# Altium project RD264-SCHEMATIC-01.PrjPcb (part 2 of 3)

## Sheet 4.SchDoc
size 420 x 297 mm
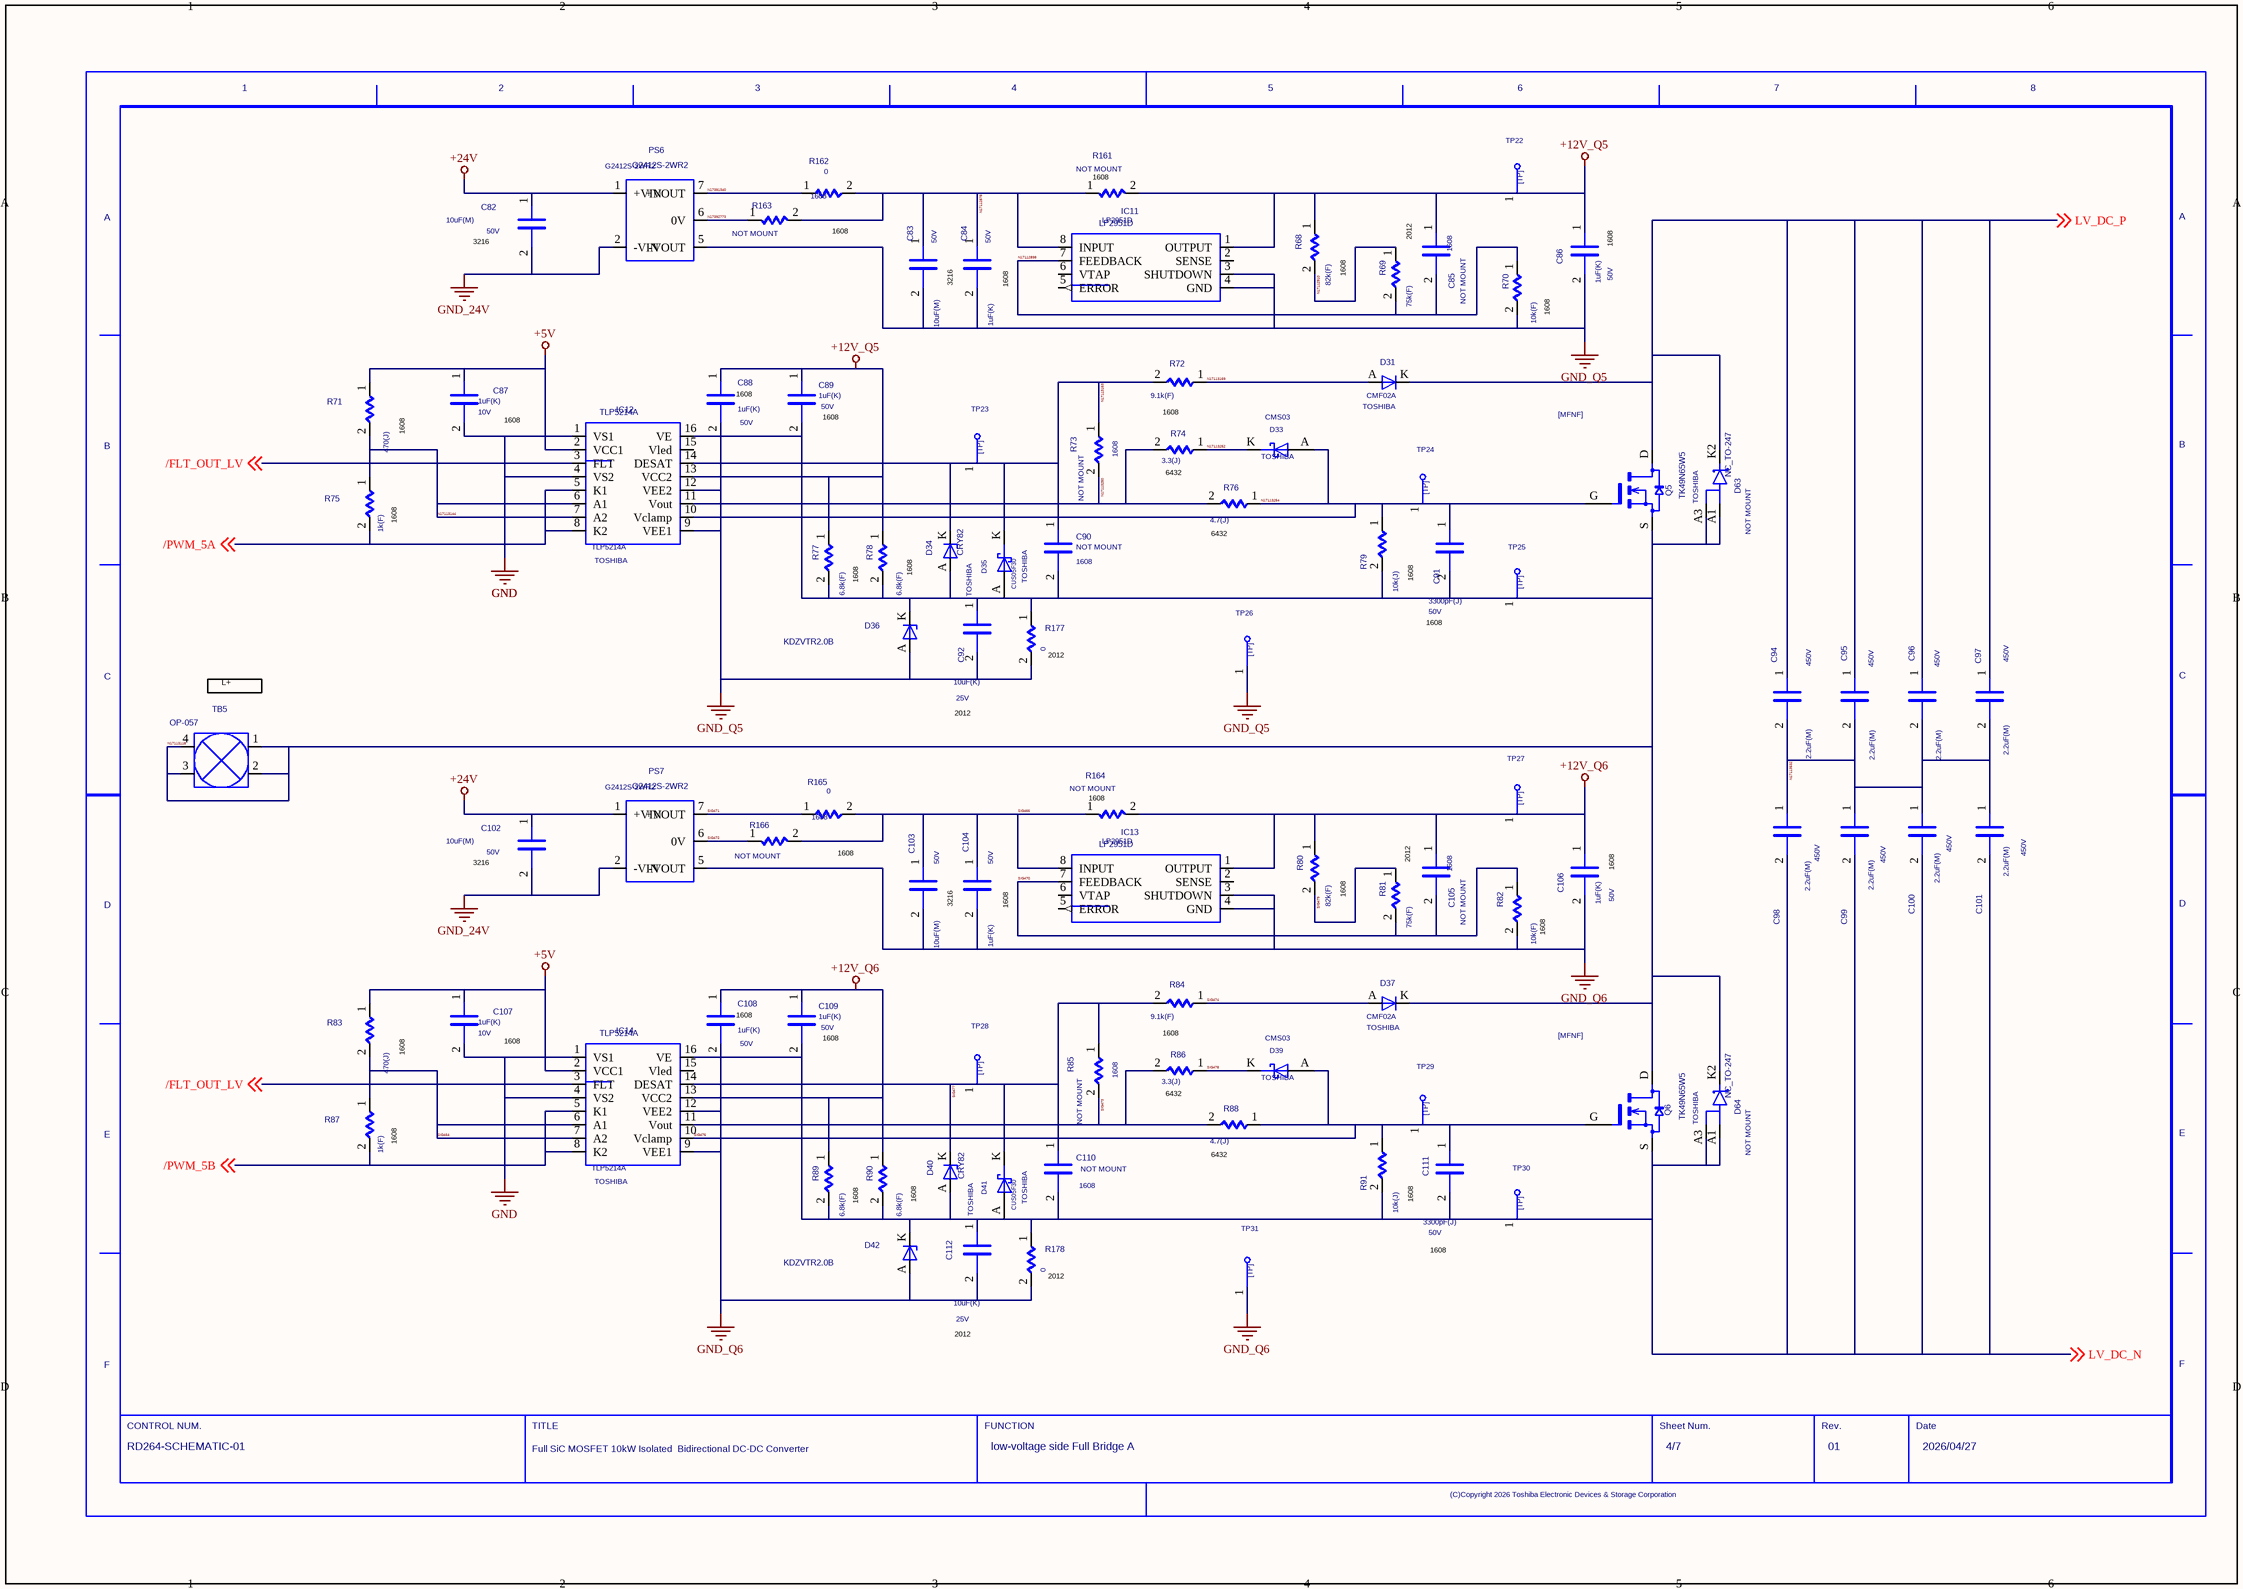
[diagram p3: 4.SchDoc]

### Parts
(Parts that share a designator on the sheet are numbered #1, #2 ... from top to bottom, then left to right.)
C82  VAL2: 50V  VAL1: 10uF(M)  (hidden comment: GRM31CR61H106MA12L)
C83  VAL2: 50V  VAL1: 10uF(M)  (hidden comment: GRM31CR61H106MA12L)
C84  VAL2: 50V  VAL1: 1uF(K)  (hidden comment: GRM188R61H105KAALD)
C85  SIZECODESMD: 1608  NOTMOUNT: NOT MOUNT  (hidden comment: NC_C1608)
C86  VAL2: 50V  VAL1: 1uF(K)  (hidden comment: GRM188R61H105KAALD)
C87  VAL2: 10V  VAL1: 1uF(K)  (hidden comment: GRM188R71A105KA61D)
C88  VAL2: 50V  VAL1: 1uF(K)  (hidden comment: GRM188R61H105KAALD)
C89  VAL2: 50V  VAL1: 1uF(K)  (hidden comment: GRM188R61H105KAALD)
C90  SIZECODESMD: 1608  NOTMOUNT: NOT MOUNT  (hidden comment: NC_C1608)
C91  VAL2: 50V  VAL1: 3300pF(J)  (hidden comment: GRM1885C1H682JA01D)
C92  VAL2: 25V  VAL1: 10uF(K)  (hidden comment: GRM21BC71E106KE11L)
C94  VAL2: 450V  VAL1: 2.2uF(M)  (hidden comment: CKG57NX7T2W225M500JH)
C95  VAL2: 450V  VAL1: 2.2uF(M)  (hidden comment: CKG57NX7T2W225M500JH)
C96  VAL2: 450V  VAL1: 2.2uF(M)  (hidden comment: CKG57NX7T2W225M500JH)
C97  VAL2: 450V  VAL1: 2.2uF(M)  (hidden comment: CKG57NX7T2W225M500JH)
C98  VAL2: 450V  VAL1: 2.2uF(M)  (hidden comment: CKG57NX7T2W225M500JH)
C99  VAL2: 450V  VAL1: 2.2uF(M)  (hidden comment: CKG57NX7T2W225M500JH)
C100  VAL2: 450V  VAL1: 2.2uF(M)  (hidden comment: CKG57NX7T2W225M500JH)
C101  VAL2: 450V  VAL1: 2.2uF(M)  (hidden comment: CKG57NX7T2W225M500JH)
C102  VAL1: 10uF(M)  VAL2: 50V  (hidden comment: GRM31CR61H106MA12L)
C103  VAL1: 10uF(M)  VAL2: 50V  (hidden comment: GRM31CR61H106MA12L)
C104  VAL1: 1uF(K)  VAL2: 50V  (hidden comment: GRM188R61H105KAALD)
C105  NOTMOUNT: NOT MOUNT  SIZECODESMD: 1608  (hidden comment: NC_C1608)
C106  VAL1: 1uF(K)  VAL2: 50V  (hidden comment: GRM188R61H105KAALD)
C107  VAL1: 1uF(K)  VAL2: 10V  (hidden comment: GRM188R71A105KA61D)
C108  VAL1: 1uF(K)  VAL2: 50V  (hidden comment: GRM188R61H105KAALD)
C109  VAL1: 1uF(K)  VAL2: 50V  (hidden comment: GRM188R61H105KAALD)
C110  NOTMOUNT: NOT MOUNT  SIZECODESMD: 1608  (hidden comment: NC_C1608)
C111  VAL2: 50V  VAL1: 3300pF(J)  (hidden comment: GRM1885C1H682JA01D)
C112  VAL1: 10uF(K)  VAL2: 25V  (hidden comment: GRM21BC71E106KE11L)
D31  USERCOMPTEXT3: TOSHIBA  VAL3: CMF02A  (hidden comment: CMF05)
D33  USERCOMPTEXT3: TOSHIBA  VAL3: CMS03  (hidden comment: SBD)
D34  CRY82  USERCOMPTEXT3: TOSHIBA
D35  USERCOMPTEXT3: TOSHIBA  VAL3: CUS05F30  (hidden comment: SBD)
D36  KDZVTR2.0B
D37  VAL3: CMF02A  USERCOMPTEXT3: TOSHIBA  (hidden comment: CMF05)
D39  USERCOMPTEXT3: TOSHIBA  VAL3: CMS03  (hidden comment: SBD)
D40  CRY82  USERCOMPTEXT3: TOSHIBA
D41  USERCOMPTEXT3: TOSHIBA  VAL3: CUS05F30  (hidden comment: SBD)
D42  KDZVTR2.0B
D63  NC_TO-247  NOTMOUNT: NOT MOUNT
D64  NC_TO-247  NOTMOUNT: NOT MOUNT
IC11  LP2951D
IC12  TLP5214A  USERCOMPTEXT3: TOSHIBA
IC13  LP2951D
IC14  TLP5214A  USERCOMPTEXT3: TOSHIBA
PS6  G2412S-2WR2
PS7  G2412S-2WR2
Q5  TK49N65W5  USERCOMPTEXT3: TOSHIBA
Q6  TK49N65W5  USERCOMPTEXT3: TOSHIBA
R68  VAL1: 82k(F)  (hidden comment: RK73H1JTTD8202F)
R69  VAL1: 75k(F)  (hidden comment: RK73H1JTTD7502F)
R70  VAL1: 10k(F)  (hidden comment: RK73H1JTTD1002F)
R71  VAL1: 470(J)  (hidden comment: RK73B1JTTD471J)
R72  VAL1: 9.1k(F)  (hidden comment: ERJ3EKF9101V)
R73  SIZECODESMD: 1608  NOTMOUNT: NOT MOUNT  (hidden comment: NC_R1608)
R74  VAL1: 3.3(J)  (hidden comment: ERJ1TYJ100U)
R75  VAL1: 1k(F)  (hidden comment: RK73H1JTTD1001F)
R76  VAL1: 4.7(J)  (hidden comment: ERJ1TYJ470U)
R77  VAL1: 6.8k(F)  (hidden comment: RK73H1JTTD6801F)
R78  VAL1: 6.8k(F)  (hidden comment: RK73H1JTTD6801F)
R79  VAL1: 10k(J)  (hidden comment: RK73B1JTTD103J)
R80  VAL1: 82k(F)  (hidden comment: RK73H1JTTD8202F)
R81  VAL1: 75k(F)  (hidden comment: RK73H1JTTD7502F)
R82  VAL1: 10k(F)  (hidden comment: RK73H1JTTD1002F)
R83  VAL1: 470(J)  (hidden comment: RK73B1JTTD471J)
R84  VAL1: 9.1k(F)  (hidden comment: ERJ3EKF9101V)
R85  NOTMOUNT: NOT MOUNT  SIZECODESMD: 1608  (hidden comment: NC_R1608)
R86  VAL1: 3.3(J)  (hidden comment: ERJ1TYJ100U)
R87  VAL1: 1k(F)  (hidden comment: RK73H1JTTD1001F)
R88  VAL1: 4.7(J)  (hidden comment: ERJ1TYJ470U)
R89  VAL1: 6.8k(F)  (hidden comment: RK73H1JTTD6801F)
R90  VAL1: 6.8k(F)  (hidden comment: RK73H1JTTD6801F)
R91  VAL1: 10k(J)  (hidden comment: RK73B1JTTD103J)
R161  NOTMOUNT: NOT MOUNT  (hidden comment: RK73Z1JTTD)
R162  VAL1: 0  SIZECODESMD: 1608  (hidden comment: NC_R1608)
R163  NOTMOUNT: NOT MOUNT  (hidden comment: RK73Z1JTTD)
R164  NOTMOUNT: NOT MOUNT  (hidden comment: RK73Z1JTTD)
R165  SIZECODESMD: 1608  VAL1: 0  (hidden comment: NC_R1608)
R166  NOTMOUNT: NOT MOUNT  (hidden comment: RK73Z1JTTD)
R177  VAL1: 0  (hidden comment: RK73Z2ATTD)
R178  VAL1: 0  (hidden comment: RK73Z2ATTD)
TB5  OP-057
TP22  TP  (value not drawn)
TP23  TP  (value not drawn)
TP24  TP  (value not drawn)
TP25  TP  (value not drawn)
TP26  TP  (value not drawn)
TP27  TP  (value not drawn)
TP28  TP  (value not drawn)
TP29  TP  (value not drawn)
TP30  TP  (value not drawn)
TP31  TP  (value not drawn)
U?#4  DATE: 2026/04/27  DRAWINGNUMBER: RD264-SCHEMATIC-01  TITLE: Full SiC MOSFET 10kW Isolated / Bidirectional DC-DC Converter  FUNCTION: low-voltage side Full Bridge A  SHEETNUMBER: 4/7  REVISION: 01  (hidden comment: WAKU_DEF100)

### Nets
+5V: C87.1 C107.1 IC12.2(VCC1) IC14.2(VCC1) R71.1 R83.1
+12V_Q5: C85.1 C86.1 C88.1 C89.1 IC11.1(OUTPUT) IC12.13(VCC2) R68.1 R77.1 R78.1 R161.2 TP22.1
+12V_Q6: C105.1 C106.1 C108.1 C109.1 IC13.1(OUTPUT) IC14.13(VCC2) R80.1 R89.1 R90.1 R164.2 TP27.1
+24V: C82.1 C102.1 PS6.1(+VIN) PS7.1(+VIN)
GND: C87.2 C107.2 IC12.1(VS1) IC12.4(VS2) IC14.1(VS1) IC14.4(VS2)
GND_24V: C82.2 C102.2 PS6.2(-VIN) PS7.2(-VIN)
GND_Q5: C83.2 C84.2 C86.2 C88.2 C92.2 D36.A IC11.3(SHUTDOWN) IC11.4(GND) IC12.9(VEE1) IC12.12(VEE2) PS6.5(-VOUT) R70.2 R177.2 TP26.1
GND_Q6: C103.2 C104.2 C106.2 C108.2 C112.2 D42.A IC13.3(SHUTDOWN) IC13.4(GND) IC14.9(VEE1) IC14.12(VEE2) PS7.5(-VOUT) R82.2 R178.2 TP31.1
/FLT_OUT_LV: IC12.3(FLT) IC14.3(FLT) ; off-sheet /FLT_OUT_LV
/PWM_5A: IC12.5(K1) IC12.8(K2) R75.2 ; off-sheet /PWM_5A
/PWM_5B: IC14.5(K1) IC14.8(K2) R87.2 ; off-sheet /PWM_5B
LV_DC_N: C98.2 C99.2 C100.2 C101.2 C109.2 C110.2 C111.2 C112.1 D40.A D41.A D42.K(C) D64.A1 D64.A3 IC14.16(VE) Q6.S R89.2 R90.2 R91.2 R178.1 TP30.1 ; off-sheet LV_DC_N
LV_DC_P: C94.1 C95.1 C96.1 C97.1 D31.K(C) D63.K2 Q5.D ; off-sheet LV_DC_P
N17112878: C83.1 C84.1 IC11.8(INPUT) R161.1 R162.2 R163.2
N17112898: C85.2 IC11.7(FEEDBACK) R69.2 R70.1
N17112910: R68.2 R69.1
N17113118: C89.2 C90.2 C91.2 C92.1 D34.A D35.A D36.K(C) D37.K(C) D63.A1 D63.A3 D64.K2 IC12.16(VE) Q5.S Q6.D R77.2 R78.2 R79.2 R177.1 TB5.1 TB5.2 TB5.3 TB5.4 TP25.1
N17113144: IC12.6(A1) IC12.7(A2) R71.2 R75.1
N17113163: C90.1 D34.K(C) D35.K(C) IC12.14(DESAT) R72.2 R73.1 TP23.1
N17113169: D31.A R72.1
N17113250: IC12.11(Vout) R73.2 R74.2 R76.2
N17113252: D33.K(C) R74.1
N17113254: C91.1 D33.A IC12.10(Vclamp) Q5.G R76.1 R79.1 TP24.1
N17113532: C94.2 C95.2 C96.2 C97.2 C98.1 C99.1 C100.1 C101.1
N17391340: PS6.7(+VOUT) R162.1
N17392773: PS6.6(0V) R163.1
SIG464: IC14.6(A1) IC14.7(A2) R83.2 R87.1
SIG466: C103.1 C104.1 IC13.8(INPUT) R164.1 R165.2 R166.2
SIG470: C105.2 IC13.7(FEEDBACK) R81.2 R82.1
SIG471: PS7.7(+VOUT) R165.1
SIG472: PS7.6(0V) R166.1
SIG473: IC14.11(Vout) R85.2 R86.2 R88.2
SIG474: D37.A R84.1
SIG476: C111.1 D39.A IC14.10(Vclamp) Q6.G R88.1 R91.1 TP29.1
SIG477: C110.1 D40.K(C) D41.K(C) IC14.14(DESAT) R84.2 R85.1 TP28.1
SIG478: D39.K(C) R86.1
SIG479: R80.2 R81.1

Not connected (* = marked no-connect by the designer): IC11 2(SENSE) 5(ERROR) 6(VTAP); IC12 15(Vled); IC13 2(SENSE) 5(ERROR) 6(VTAP); IC14 15(Vled)

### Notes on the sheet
- (near R161) 1608
- (near C82) 3216
- 1608
- 2012
- (near C86) 1608
- 3216
- (near C84) 1608
- (near R68) 1608
- (near C88) 1608
- (near R71) 1608
- (near C87) 1608
- (near C89) 1608
- (near R75) 1608
- (near R74) 6432
- (near R76) 6432
- (near R177) 2012
- L+
- (near R164) 1608
- (near C102) 3216
- (near C106) 1608
- (near C104) 1608
- (near R80) 1608
- (near R82) 1608
- (near R83) 1608
- (near C107) 1608
- (near C108) 1608
- (near C109) 1608
- (near R87) 1608
- (near R86) 6432
- (near R88) 6432
- (near R178) 2012

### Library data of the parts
C82 = C_Dup1: ORIGINALSYMBOLORIGIN: (0,4826); COMP: C-GRM31CR61H106MA12L; TIME: 14:31:23; UPDATEUSER: t5459927; SAVECOUNT: 1; NOTE: 10uF 50V; FUNCN: C_C.Normal_package; REFERENCE TEMPLATE: C; INSTANCENAME: INS17112921
C83 = C_Dup1: ORIGINALSYMBOLORIGIN: (0,4826); COMP: C-GRM31CR61H106MA12L; TIME: 14:31:23; UPDATEUSER: t5459927; SAVECOUNT: 1; NOTE: 10uF 50V; FUNCN: C_C.Normal_package; REFERENCE TEMPLATE: C; INSTANCENAME: INS17112929
C84 = C_Dup1: ORIGINALSYMBOLORIGIN: (0,4826); COMP: C-GRM188R61H105KAALD; TIME: 14:31:23; UPDATEUSER: t5459927; SAVECOUNT: 1; NOTE: 1uF 50V; FUNCN: C_C.Normal_package; REFERENCE TEMPLATE: C; INSTANCENAME: INS17112937
C85 = C_Dup1: ORIGINALSYMBOLORIGIN: (0,4826); COMP: C-1608_NM; TIME: 14:31:23; UPDATEUSER: t5459927; SAVECOUNT: 1; FUNCN: C_C.Normal_package; REFERENCE TEMPLATE: C; INSTANCENAME: INS17112913
C86 = C_Dup1: ORIGINALSYMBOLORIGIN: (0,4826); COMP: C-GRM188R61H105KAALD; TIME: 14:31:23; UPDATEUSER: t5459927; SAVECOUNT: 1; NOTE: 1uF 50V; FUNCN: C_C.Normal_package; REFERENCE TEMPLATE: C; INSTANCENAME: INS17112961
C87 = C_Dup1: ORIGINALSYMBOLORIGIN: (0,4826); COMP: C-GRM188R71A105KA61D; TIME: 14:31:23; UPDATEUSER: t5459927; SAVECOUNT: 1; NOTE: 1uF 10V; FUNCN: C_C.Normal_package; REFERENCE TEMPLATE: C; INSTANCENAME: INS17113085
C88 = C_Dup1: ORIGINALSYMBOLORIGIN: (0,4826); COMP: C-GRM188R61H105KAALD; TIME: 14:31:23; UPDATEUSER: t5459927; SAVECOUNT: 1; NOTE: 1uF 50V; FUNCN: C_C.Normal_package; REFERENCE TEMPLATE: C; INSTANCENAME: INS17113061
C89 = C_Dup1: ORIGINALSYMBOLORIGIN: (0,4826); COMP: C-GRM188R61H105KAALD; TIME: 14:31:23; UPDATEUSER: t5459927; SAVECOUNT: 1; NOTE: 1uF 50V; FUNCN: C_C.Normal_package; REFERENCE TEMPLATE: C; INSTANCENAME: INS17113069
C90 = C_Dup1: ORIGINALSYMBOLORIGIN: (0,4826); COMP: C-1608_NM; TIME: 14:31:23; UPDATEUSER: t5459927; SAVECOUNT: 1; FUNCN: C_C.Normal_package; REFERENCE TEMPLATE: C; INSTANCENAME: INS17113388
C91 C111 = C_Dup1: ORIGINALSYMBOLORIGIN: (0,4826); COMP: C-GRM1885C1H682JA01D; TIME: 14:31:23; UPDATEUSER: t5459927; SAVECOUNT: 1; NOTE: 6800pF 50V; FUNCN: C_C.Normal_package; REFERENCE TEMPLATE: C; INSTANCENAME: INS17753463
C92 = C_Dup1: ORIGINALSYMBOLORIGIN: (0,4826); COMP: C-GRM21BC71E106KE11L; TIME: 14:31:23; UPDATEUSER: t5459927; SAVECOUNT: 1; NOTE: 10uF 25V; FUNCN: C_C.Normal_package; REFERENCE TEMPLATE: C; INSTANCENAME: INS17895207
C94 = C_Dup1: ORIGINALSYMBOLORIGIN: (0,4826); COMP: C-CKG57NX7T2W225M500JH; TIME: 14:31:23; UPDATEUSER: t5459927; SAVECOUNT: 1; NOTE: 2.2uF 450V; FUNCN: C_C.Normal_package; REFERENCE TEMPLATE: C; INSTANCENAME: INS17255321
C95 = C_Dup1: ORIGINALSYMBOLORIGIN: (0,4826); COMP: C-CKG57NX7T2W225M500JH; TIME: 14:31:23; UPDATEUSER: t5459927; SAVECOUNT: 1; NOTE: 2.2uF 450V; FUNCN: C_C.Normal_package; REFERENCE TEMPLATE: C; INSTANCENAME: INS17255582
C96 = C_Dup1: ORIGINALSYMBOLORIGIN: (0,4826); COMP: C-CKG57NX7T2W225M500JH; TIME: 14:31:23; UPDATEUSER: t5459927; SAVECOUNT: 1; NOTE: 2.2uF 450V; FUNCN: C_C.Normal_package; REFERENCE TEMPLATE: C; INSTANCENAME: INS17255645
C97 = C_Dup1: ORIGINALSYMBOLORIGIN: (0,4826); COMP: C-CKG57NX7T2W225M500JH; TIME: 14:31:23; UPDATEUSER: t5459927; SAVECOUNT: 1; NOTE: 2.2uF 450V; FUNCN: C_C.Normal_package; REFERENCE TEMPLATE: C; INSTANCENAME: INS17255762
C98 = C_Dup1: ORIGINALSYMBOLORIGIN: (0,4826); COMP: C-CKG57NX7T2W225M500JH; TIME: 14:31:23; UPDATEUSER: t5459927; SAVECOUNT: 1; NOTE: 2.2uF 450V; FUNCN: C_C.Normal_package; REFERENCE TEMPLATE: C; INSTANCENAME: INS17255916
C99 = C_Dup1: ORIGINALSYMBOLORIGIN: (0,4826); COMP: C-CKG57NX7T2W225M500JH; TIME: 14:31:23; UPDATEUSER: t5459927; SAVECOUNT: 1; NOTE: 2.2uF 450V; FUNCN: C_C.Normal_package; REFERENCE TEMPLATE: C; INSTANCENAME: INS17256105
C100 = C_Dup1: ORIGINALSYMBOLORIGIN: (0,4826); COMP: C-CKG57NX7T2W225M500JH; TIME: 14:31:23; UPDATEUSER: t5459927; SAVECOUNT: 1; NOTE: 2.2uF 450V; FUNCN: C_C.Normal_package; REFERENCE TEMPLATE: C; INSTANCENAME: INS17256431
C101 = C_Dup1: ORIGINALSYMBOLORIGIN: (0,4826); COMP: C-CKG57NX7T2W225M500JH; TIME: 14:31:23; UPDATEUSER: t5459927; SAVECOUNT: 1; NOTE: 2.2uF 450V; FUNCN: C_C.Normal_package; REFERENCE TEMPLATE: C; INSTANCENAME: INS17256618
C102 = C_Dup1: ORIGINALSYMBOLORIGIN: (0,4826); COMP: C-GRM31CR61H106MA12L; TIME: 14:31:23; UPDATEUSER: t5459927; SAVECOUNT: 1; INSTANCENAME: INS17112921; REFERENCE TEMPLATE: C; COMPONENTNAME: C_C.Normal_package; NOTE: 10uF 50V
C103 = C_Dup1: ORIGINALSYMBOLORIGIN: (0,4826); COMP: C-GRM31CR61H106MA12L; TIME: 14:31:23; UPDATEUSER: t5459927; SAVECOUNT: 1; INSTANCENAME: INS17112929; REFERENCE TEMPLATE: C; COMPONENTNAME: C_C.Normal_package; NOTE: 10uF 50V
C104 = C_Dup1: ORIGINALSYMBOLORIGIN: (0,4826); COMP: C-GRM188R61H105KAALD; TIME: 14:31:23; UPDATEUSER: t5459927; SAVECOUNT: 1; INSTANCENAME: INS17112937; REFERENCE TEMPLATE: C; COMPONENTNAME: C_C.Normal_package; NOTE: 1uF 50V
C105 = C_Dup1: ORIGINALSYMBOLORIGIN: (0,4826); COMP: C-1608_NM; TIME: 14:31:23; UPDATEUSER: t5459927; SAVECOUNT: 1; INSTANCENAME: INS17112913; REFERENCE TEMPLATE: C; COMPONENTNAME: C_C.Normal_package
C106 = C_Dup1: ORIGINALSYMBOLORIGIN: (0,4826); COMP: C-GRM188R61H105KAALD; TIME: 14:31:23; UPDATEUSER: t5459927; SAVECOUNT: 1; INSTANCENAME: INS17112961; REFERENCE TEMPLATE: C; COMPONENTNAME: C_C.Normal_package; NOTE: 1uF 50V
C107 = C_Dup1: ORIGINALSYMBOLORIGIN: (0,4826); COMP: C-GRM188R71A105KA61D; TIME: 14:31:23; UPDATEUSER: t5459927; SAVECOUNT: 1; INSTANCENAME: INS17113085; REFERENCE TEMPLATE: C; COMPONENTNAME: C_C.Normal_package; NOTE: 1uF 10V
C108 = C_Dup1: ORIGINALSYMBOLORIGIN: (0,4826); COMP: C-GRM188R61H105KAALD; TIME: 14:31:23; UPDATEUSER: t5459927; SAVECOUNT: 1; INSTANCENAME: INS17113061; REFERENCE TEMPLATE: C; COMPONENTNAME: C_C.Normal_package; NOTE: 1uF 50V
C109 = C_Dup1: ORIGINALSYMBOLORIGIN: (0,4826); COMP: C-GRM188R61H105KAALD; TIME: 14:31:23; UPDATEUSER: t5459927; SAVECOUNT: 1; INSTANCENAME: INS17113069; REFERENCE TEMPLATE: C; COMPONENTNAME: C_C.Normal_package; NOTE: 1uF 50V
C110 = C_Dup1: ORIGINALSYMBOLORIGIN: (0,4826); COMP: C-1608_NM; TIME: 14:31:23; UPDATEUSER: t5459927; SAVECOUNT: 1; INSTANCENAME: INS17113388; REFERENCE TEMPLATE: C; COMPONENTNAME: C_C.Normal_package
C112 = C_Dup1: ORIGINALSYMBOLORIGIN: (0,4826); COMP: C-GRM21BC71E106KE11L; TIME: 14:31:23; UPDATEUSER: t5459927; SAVECOUNT: 1; INSTANCENAME: INS17895207; REFERENCE TEMPLATE: C; COMPONENTNAME: C_C.Normal_package; NOTE: 10uF 25V
D31 = D: UPDATEUSER: t5459927; COMP: D-CMF05; UPDATETIME: 14:31:23; SAVECOUNT: 1; SAVEAREA0: -225,-91,12804,7836; ORIGINALSYMBOLORIGIN: (0,0); FUNCN: D_D.Normal_package; INSTANCENAME: INS17279788
D33 D35 D39 D41 = SBD: SAVEAREA0: -4630,-153,17114,13055; TIME: 14:49:55; UPDATEUSER: fukuda-y; UPDATETIME: 08:16:22; SAVECOUNT: 9; OriginalSymbolOrigin: (5080,5080)
D34 D40 = ZD: UPDATEUSER: t5459927; COMP: D-CRY82; UPDATETIME: 14:31:23; SAVECOUNT: 1; SAVEAREA0: -4630,-153,17114,13055; ORIGINALSYMBOLORIGIN: (0,0); FUNCN: ZD_ZD.Normal_package; INSTANCENAME: INS17317417
D36 D42 = ZD: UPDATEUSER: t5459927; COMP: D-KDZVTR2.0B; UPDATETIME: 14:31:23; SAVECOUNT: 1; SAVEAREA0: -4630,-153,17114,13055; ORIGINALSYMBOLORIGIN: (0,0); COMPONENTNAME: ZD_ZD.Normal_package; REFERENCE TEMPLATE: D; INSTANCENAME: INS17385836
D37 = D: UPDATEUSER: t5459927; COMP: D-CMF05; UPDATETIME: 14:31:23; SAVECOUNT: 1; SAVEAREA0: -225,-91,12804,7836; ORIGINALSYMBOLORIGIN: (0,0); INSTANCENAME: INS17279788; COMPONENTNAME: D_D.Normal_package
D63 D64 = NC_TO_247: Schottky Barrier Diode; COMP: D-TO-247_NM; MAKER: NC; TIME: 14:31:25; UPDATEUSER: t5459927; SAVECOUNT: 1; OriginalSymbolOrigin: (0,0); VAL3: TO-247; FUNCN: NC_TO-247_NC_TO-247.Normal_package; INSTANCENAME: INS17322987
IC11 IC13 = LP2951D: IC Regurator; COMP: IC-LP2951D_NM; MAKER: Txsas Instruments; TIME: 14:31:24; UPDATEUSER: t5459927; UPDATETIME: 14:27:00; SAVECOUNT: 3; SAVEAREA0: -6711,-14463,34014,2574; OriginalSymbolOrigin: (0,0); NOTMOUNT: MOUNT
IC12 IC14 = TLP5214A: Gate Driver; COMP: IC-TLP5214A; TIME: 14:31:24; UPDATEUSER: t5459927; UPDATETIME: 14:29:17; SAVECOUNT: 3; SAVEAREA0: -11000,-19257,28193,-2860; OriginalSymbolOrigin: (0,0)
PS6 PS7 = G2412S_2WR2: DCDC Converter; COMP: PS-G2412S-2WR2; MAKER: MORNSUN; NOTE: 24Vin ｱ12Vout; TIME: 14:31:25; UPDATEUSER: t5459927; UPDATETIME: 15:22:21; SAVECOUNT: 2; SAVEAREA0: -5083,-7378,17282,9018; OriginalSymbolOrigin: (0,0)
Q5 = MFNF: PART NUMBER: TMP-432; SAVEAREA0: -7027,-292,21786,15988; ORIGINALSYMBOLORIGIN: (0,0); COMP: TW048N65C; SAVECOUNT: 1; TIME: 14:31:23; UPDATEUSER: t5459927; FUNCN: MFNF_MFNF.Normal_package; REFERENCE TEMPLATE: Q; INSTANCENAME: INS17254361
Q6 = MFNF: PART NUMBER: TMP-432; SAVEAREA0: -7027,-292,21786,15988; ORIGINALSYMBOLORIGIN: (0,0); COMP: TW048N65C; SAVECOUNT: 1; TIME: 14:31:23; UPDATEUSER: t5459927; INSTANCENAME: INS17254361; REFERENCE TEMPLATE: Q; COMPONENTNAME: MFNF_MFNF.Normal_package
R68 = R: ORIGINALSYMBOLORIGIN: (0,0); COMP: R-RK73H1JTTD8202F; TIME: 14:31:23; UPDATEUSER: t5459927; SAVECOUNT: 1; VAL2: 100mw; NOTE: 82kohm 0.1W; FUNCN: R_R.Normal_package; INSTANCENAME: INS17112901
R69 = R: ORIGINALSYMBOLORIGIN: (0,0); COMP: R-RK73H1JTTD7502F; TIME: 14:31:23; UPDATEUSER: t5459927; SAVECOUNT: 1; VAL2: 100mw; NOTE: 75kohm 0.1W; FUNCN: R_R.Normal_package; INSTANCENAME: INS17112949
R70 = R: ORIGINALSYMBOLORIGIN: (0,0); COMP: R-RK73H1JTTD1002F; TIME: 14:31:23; UPDATEUSER: t5459927; SAVECOUNT: 1; VAL2: 100mw; NOTE: 10kohm 0.1W; FUNCN: R_R.Normal_package; INSTANCENAME: INS17112973
R71 = R: ORIGINALSYMBOLORIGIN: (0,0); COMP: R-RK73B1JTTD471J; TIME: 14:31:23; UPDATEUSER: t5459927; SAVECOUNT: 1; VAL2: 125mw; NOTE: 470ohm 0.1W; FUNCN: R_R.Normal_package; INSTANCENAME: INS17113077
R72 = R: PART NUMBER: TMP-429; ORIGINALSYMBOLORIGIN: (0,0); COMP: R-ERJ3EKF9101V; TIME: 14:31:23; UPDATEUSER: t5459927; SAVECOUNT: 1; VAL2: 100mw; NOTE: 9.1kohm 0.1W; FUNCN: R_R.Normal_package; INSTANCENAME: INS17253791
R73 = R: ORIGINALSYMBOLORIGIN: (0,0); COMP: R-1608_NM; TIME: 14:31:23; UPDATEUSER: t5459927; SAVECOUNT: 1; FUNCN: R_R.Normal_package; INSTANCENAME: INS17113188
R74 = R: ORIGINALSYMBOLORIGIN: (0,0); COMP: R-ERJ1TYJ100U; TIME: 14:31:23; UPDATEUSER: t5459927; SAVECOUNT: 1; VAL2: 1w; NOTE: 10ohm 1W; FUNCN: R_R.Normal_package; INSTANCENAME: INS17253884
R75 = R: ORIGINALSYMBOLORIGIN: (0,0); COMP: R-RK73H1JTTD1001F; TIME: 14:31:23; UPDATEUSER: t5459927; SAVECOUNT: 1; VAL2: 125mw; NOTE: 1.0kohm 0.1W; FUNCN: R_R.Normal_package; INSTANCENAME: INS17113262
R76 R88 = R: PART NUMBER: TMP-902; ORIGINALSYMBOLORIGIN: (0,0); COMP: R-ERJ1TYJ470U; TIME: 14:31:23; UPDATEUSER: t5459927; SAVECOUNT: 1; VAL2: 1w; NOTE: 47ohm 1W; FUNCN: R_R.Normal_package; INSTANCENAME: INS17753183
R77 = R: ORIGINALSYMBOLORIGIN: (0,0); COMP: R-RK73H1JTTD6801F; TIME: 14:31:23; UPDATEUSER: t5459927; SAVECOUNT: 1; VAL2: 100mw; NOTE: 6.8kohm 0.1W; FUNCN: R_R.Normal_package; INSTANCENAME: INS17113356
R78 = R: ORIGINALSYMBOLORIGIN: (0,0); COMP: R-RK73H1JTTD6801F; TIME: 14:31:23; UPDATEUSER: t5459927; SAVECOUNT: 1; VAL2: 100mw; NOTE: 6.8kohm 0.1W; FUNCN: R_R.Normal_package; INSTANCENAME: INS17113364
R79 = R: ORIGINALSYMBOLORIGIN: (0,0); COMP: R-RK73B1JTTD103J; TIME: 14:31:23; UPDATEUSER: t5459927; SAVECOUNT: 1; VAL2: 100mw; NOTE: 10kohm 0.1W; FUNCN: R_R.Normal_package; INSTANCENAME: INS17113334
R80 = R: ORIGINALSYMBOLORIGIN: (0,0); COMP: R-RK73H1JTTD8202F; TIME: 14:31:23; UPDATEUSER: t5459927; SAVECOUNT: 1; INSTANCENAME: INS17112901; COMPONENTNAME: R_R.Normal_package; NOTE: 82kohm 0.1W; VAL2: 100mw
R81 = R: ORIGINALSYMBOLORIGIN: (0,0); COMP: R-RK73H1JTTD7502F; TIME: 14:31:23; UPDATEUSER: t5459927; SAVECOUNT: 1; INSTANCENAME: INS17112949; COMPONENTNAME: R_R.Normal_package; NOTE: 75kohm 0.1W; VAL2: 100mw
R82 = R: ORIGINALSYMBOLORIGIN: (0,0); COMP: R-RK73H1JTTD1002F; TIME: 14:31:23; UPDATEUSER: t5459927; SAVECOUNT: 1; INSTANCENAME: INS17112973; COMPONENTNAME: R_R.Normal_package; NOTE: 10kohm 0.1W; VAL2: 100mw
R83 = R: ORIGINALSYMBOLORIGIN: (0,0); COMP: R-RK73B1JTTD471J; TIME: 14:31:23; UPDATEUSER: t5459927; SAVECOUNT: 1; INSTANCENAME: INS17113077; COMPONENTNAME: R_R.Normal_package; NOTE: 470ohm 0.1W; VAL2: 125mw
R84 = R: PART NUMBER: TMP-429; ORIGINALSYMBOLORIGIN: (0,0); COMP: R-ERJ3EKF9101V; TIME: 14:31:23; UPDATEUSER: t5459927; SAVECOUNT: 1; INSTANCENAME: INS17253791; COMPONENTNAME: R_R.Normal_package; NOTE: 9.1kohm 0.1W; VAL2: 100mw
R85 = R: ORIGINALSYMBOLORIGIN: (0,0); COMP: R-1608_NM; TIME: 14:31:23; UPDATEUSER: t5459927; SAVECOUNT: 1; INSTANCENAME: INS17113188; COMPONENTNAME: R_R.Normal_package
R86 = R: ORIGINALSYMBOLORIGIN: (0,0); COMP: R-ERJ1TYJ100U; TIME: 14:31:23; UPDATEUSER: t5459927; SAVECOUNT: 1; INSTANCENAME: INS17253884; COMPONENTNAME: R_R.Normal_package; NOTE: 10ohm 1W; VAL2: 1w
R87 = R: ORIGINALSYMBOLORIGIN: (0,0); COMP: R-RK73H1JTTD1001F; TIME: 14:31:23; UPDATEUSER: t5459927; SAVECOUNT: 1; INSTANCENAME: INS17113262; COMPONENTNAME: R_R.Normal_package; NOTE: 1.0kohm 0.1W; VAL2: 125mw
R89 = R: ORIGINALSYMBOLORIGIN: (0,0); COMP: R-RK73H1JTTD6801F; TIME: 14:31:23; UPDATEUSER: t5459927; SAVECOUNT: 1; INSTANCENAME: INS17113356; COMPONENTNAME: R_R.Normal_package; NOTE: 6.8kohm 0.1W; VAL2: 100mw
R90 = R: ORIGINALSYMBOLORIGIN: (0,0); COMP: R-RK73H1JTTD6801F; TIME: 14:31:23; UPDATEUSER: t5459927; SAVECOUNT: 1; INSTANCENAME: INS17113364; COMPONENTNAME: R_R.Normal_package; NOTE: 6.8kohm 0.1W; VAL2: 100mw
R91 = R: ORIGINALSYMBOLORIGIN: (0,0); COMP: R-RK73B1JTTD103J; TIME: 14:31:23; UPDATEUSER: t5459927; SAVECOUNT: 1; INSTANCENAME: INS17113334; COMPONENTNAME: R_R.Normal_package; NOTE: 10kohm 0.1W; VAL2: 100mw
R161 = R: ORIGINALSYMBOLORIGIN: (0,0); COMP: R-RK73Z1JTTD; TIME: 14:31:23; UPDATEUSER: t5459927; SAVECOUNT: 1; NOTE: 0ohm 0.1W; FUNCN: R_R.Normal_package; INSTANCENAME: INS17390327
R162 = R: ORIGINALSYMBOLORIGIN: (0,0); COMP: R-1608_NM; TIME: 14:31:23; UPDATEUSER: t5459927; SAVECOUNT: 1; NOTMOUNT: MOUNT; FUNCN: R_R.Normal_package; INSTANCENAME: INS17391865
R163 = R: ORIGINALSYMBOLORIGIN: (0,0); COMP: R-RK73Z1JTTD; TIME: 14:31:23; UPDATEUSER: t5459927; SAVECOUNT: 1; NOTE: 0ohm 0.1W; FUNCN: R_R.Normal_package; INSTANCENAME: INS17391891
R164 = R: ORIGINALSYMBOLORIGIN: (0,0); COMP: R-RK73Z1JTTD; TIME: 14:31:23; UPDATEUSER: t5459927; SAVECOUNT: 1; INSTANCENAME: INS17390327; COMPONENTNAME: R_R.Normal_package; NOTE: 0ohm 0.1W
R165 = R: ORIGINALSYMBOLORIGIN: (0,0); COMP: R-1608_NM; TIME: 14:31:23; UPDATEUSER: t5459927; SAVECOUNT: 1; INSTANCENAME: INS17391865; COMPONENTNAME: R_R.Normal_package; NOTMOUNT: MOUNT
R166 = R: ORIGINALSYMBOLORIGIN: (0,0); COMP: R-RK73Z1JTTD; TIME: 14:31:23; UPDATEUSER: t5459927; SAVECOUNT: 1; INSTANCENAME: INS17391891; COMPONENTNAME: R_R.Normal_package; NOTE: 0ohm 0.1W
R177 = R: ORIGINALSYMBOLORIGIN: (0,0); COMP: R-RK73Z2ATTD; TIME: 14:31:23; UPDATEUSER: t5459927; SAVECOUNT: 1; NOTE: 0ohm 0.25w; FUNCN: R_R.Normal_package; INSTANCENAME: INS17894887
R178 = R: ORIGINALSYMBOLORIGIN: (0,0); COMP: R-RK73Z2ATTD; TIME: 14:31:23; UPDATEUSER: t5459927; SAVECOUNT: 1; INSTANCENAME: INS17894887; COMPONENTNAME: R_R.Normal_package; NOTE: 0ohm 0.25w
TB5 = OP_057: Terminal Block; PART NUMBER: TMP-784; COMP: TB-OP-057; MAKER: Osada; NOTE: 85A M5; TIME: 14:31:25; UPDATEUSER: t5459927; SAVECOUNT: 1; SAVEAREA0: -3160,-10780,12927,1014; OriginalSymbolOrigin: (0,0); FUNCN: OP-057_OP-057.Normal_package; REFERENCE TEMPLATE: TB; INSTANCENAME: INS17364097
TP22-TP31 = TP: TIME: 16:12:21; UPDATEUSER: fukuda-y; UPDATETIME: 16:18:11; SAVECOUNT: 2; SAVEAREA0: -242,-92,12810,7836; OriginalSymbolOrigin: (0,7620); VAL3: HK-3-G; COMP: TP-HK-3-G
U?#4 = WAKU_DEF100: PLOTTIME: HH:MM; SAVEAREA0: 204655,-40163,430411,63902; TIME: 14:30:25; UPDATEUSER: t5459927; UPDATETIME: 14:22:34; SAVECOUNT: 7; OriginalSymbolOrigin: (10160,284480); SHTSAVECOUNT: 18

## Sheet 5.SchDoc
size 420 x 297 mm
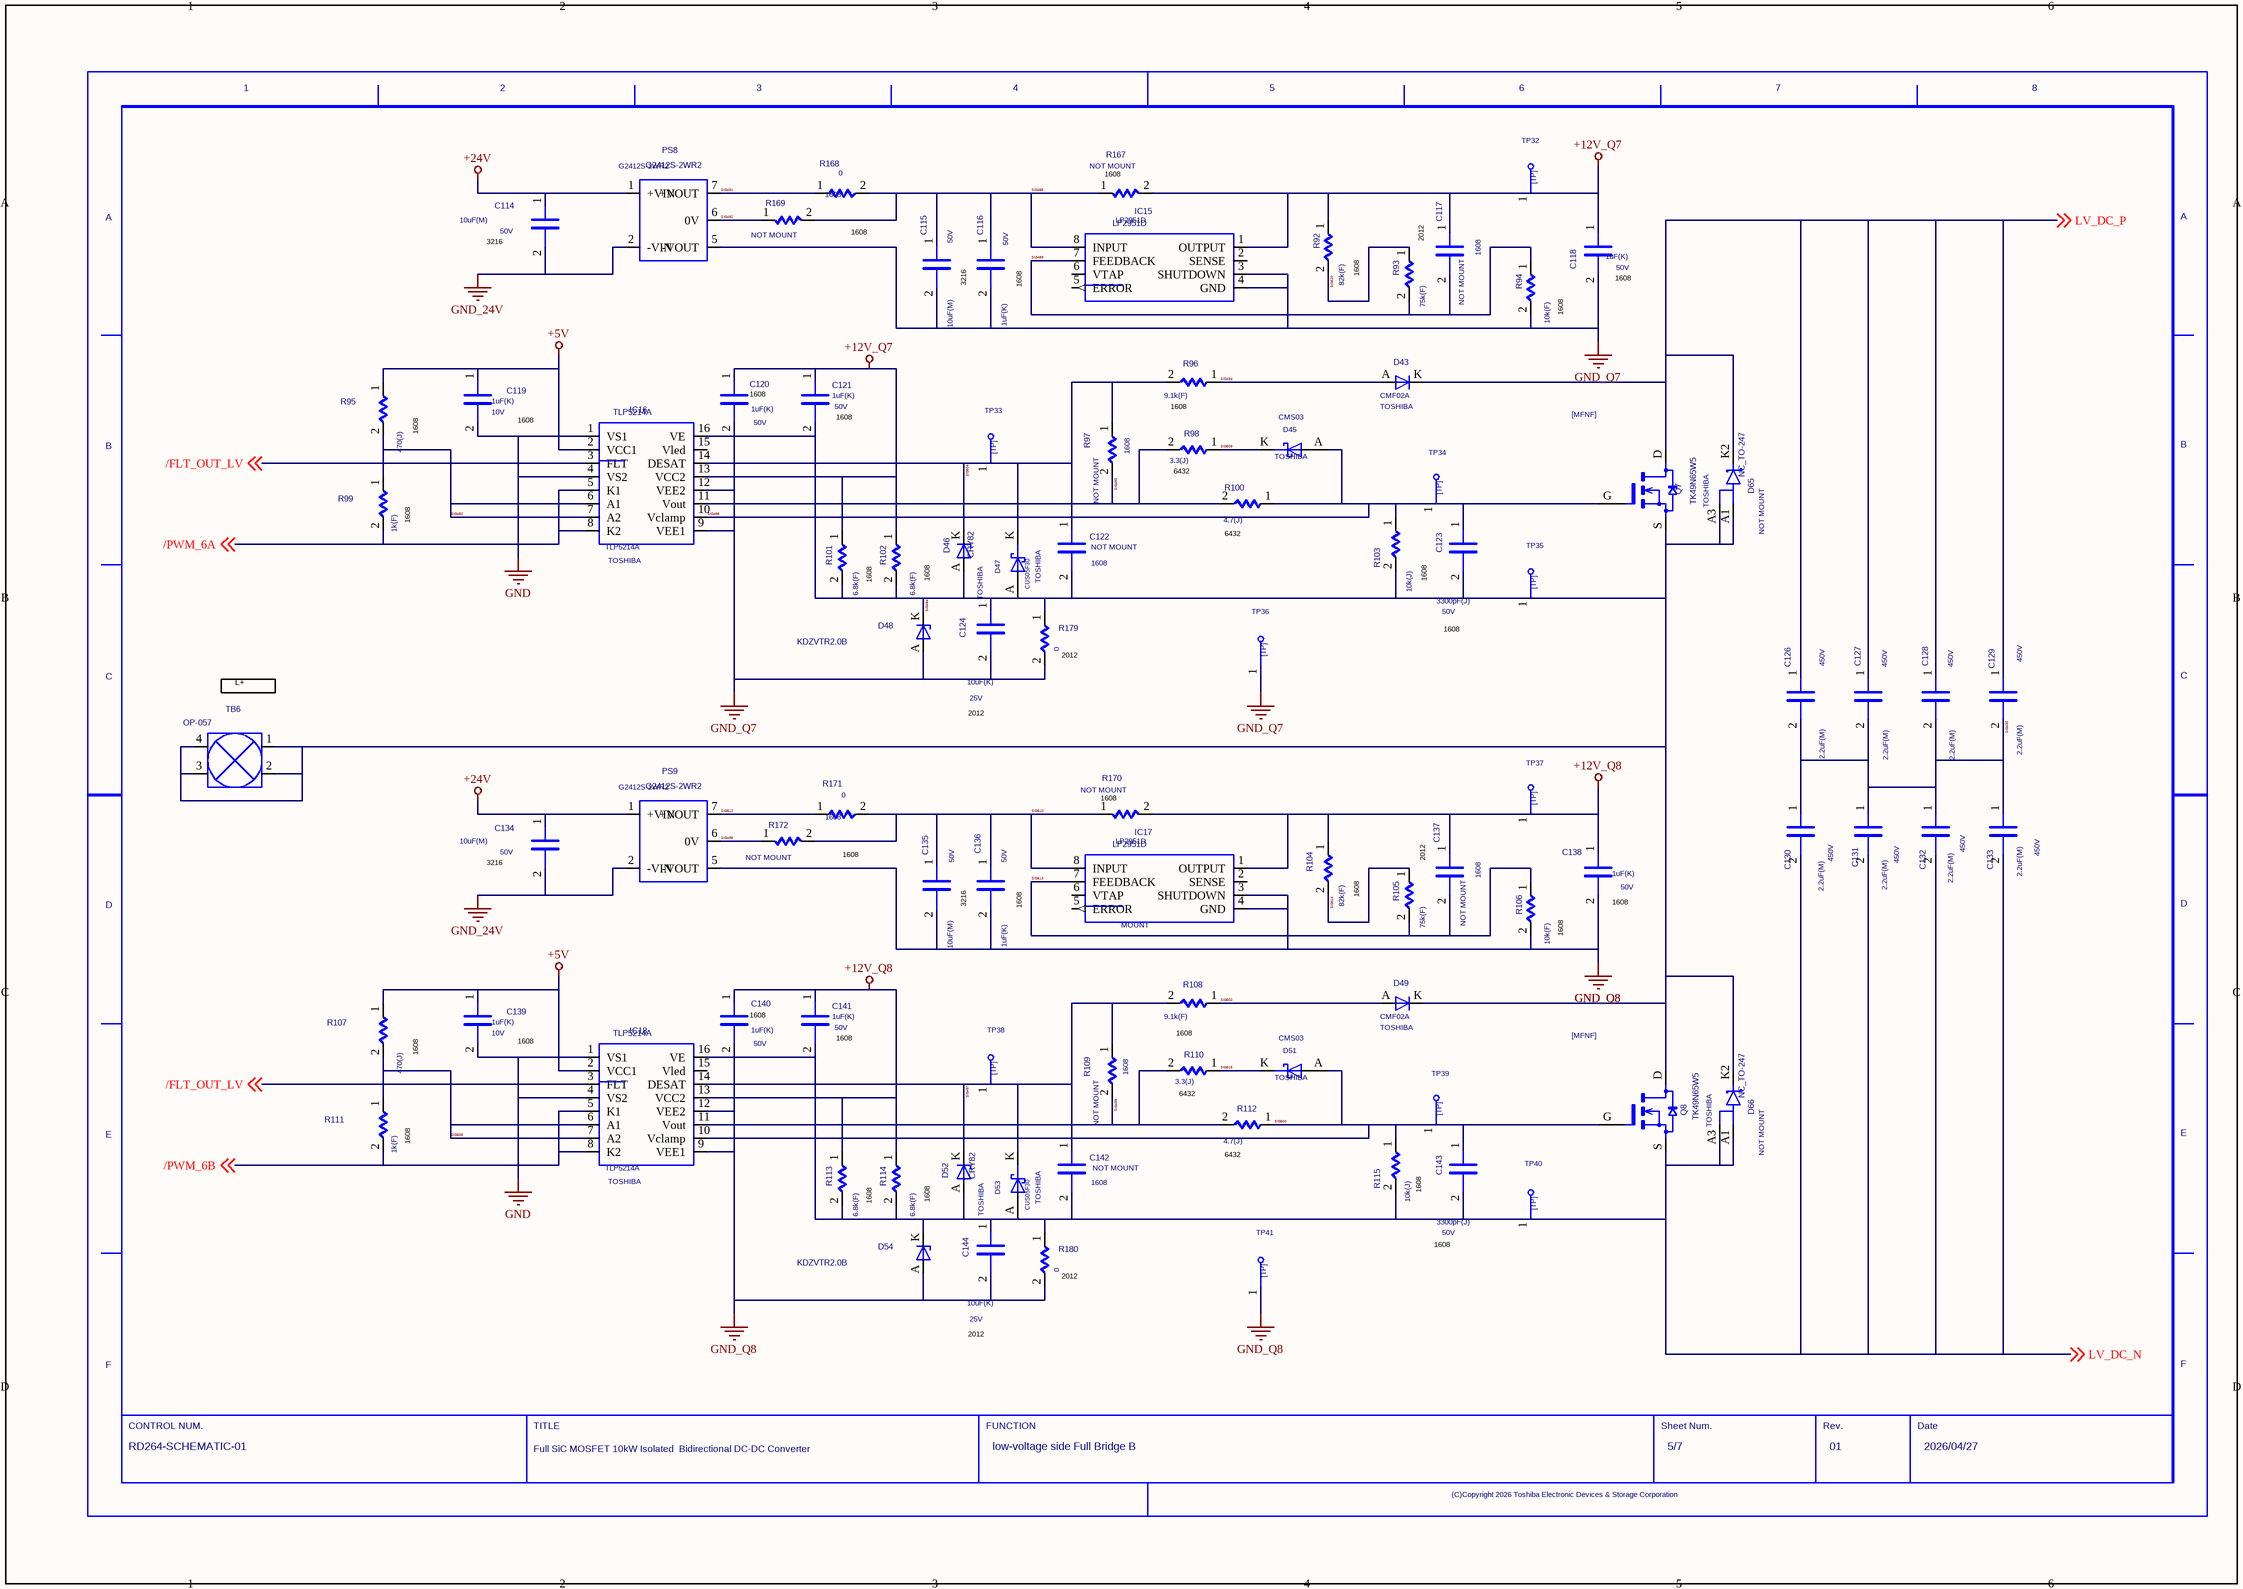
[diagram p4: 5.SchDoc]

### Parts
(Parts that share a designator on the sheet are numbered #1, #2 ... from top to bottom, then left to right.)
C114  VAL2: 50V  VAL1: 10uF(M)  (hidden comment: GRM31CR61H106MA12L)
C115  VAL1: 10uF(M)  VAL2: 50V  (hidden comment: GRM31CR61H106MA12L)
C116  VAL1: 1uF(K)  VAL2: 50V  (hidden comment: GRM188R61H105KAALD)
C117  NOTMOUNT: NOT MOUNT  SIZECODESMD: 1608  (hidden comment: NC_C1608)
C118  VAL1: 1uF(K)  VAL2: 50V  (hidden comment: GRM188R61H105KAALD)
C119  VAL1: 1uF(K)  VAL2: 10V  (hidden comment: GRM188R71A105KA61D)
C120  VAL1: 1uF(K)  VAL2: 50V  (hidden comment: GRM188R61H105KAALD)
C121  VAL1: 1uF(K)  VAL2: 50V  (hidden comment: GRM188R61H105KAALD)
C122  NOTMOUNT: NOT MOUNT  SIZECODESMD: 1608  (hidden comment: NC_C1608)
C123  VAL2: 50V  VAL1: 3300pF(J)  (hidden comment: GRM1885C1H682JA01D)
C124  VAL2: 25V  VAL1: 10uF(K)  (hidden comment: GRM21BC71E106KE11L)
C126  VAL1: 2.2uF(M)  VAL2: 450V  (hidden comment: CKG57NX7T2W225M500JH)
C127  VAL2: 450V  VAL1: 2.2uF(M)  (hidden comment: CKG57NX7T2W225M500JH)
C128  VAL1: 2.2uF(M)  VAL2: 450V  (hidden comment: CKG57NX7T2W225M500JH)
C129  VAL1: 2.2uF(M)  VAL2: 450V  (hidden comment: CKG57NX7T2W225M500JH)
C130  VAL1: 2.2uF(M)  VAL2: 450V  (hidden comment: CKG57NX7T2W225M500JH)
C131  VAL1: 2.2uF(M)  VAL2: 450V  (hidden comment: CKG57NX7T2W225M500JH)
C132  VAL2: 450V  VAL1: 2.2uF(M)  (hidden comment: CKG57NX7T2W225M500JH)
C133  VAL1: 2.2uF(M)  VAL2: 450V  (hidden comment: CKG57NX7T2W225M500JH)
C134  VAL1: 10uF(M)  VAL2: 50V  (hidden comment: GRM31CR61H106MA12L)
C135  VAL1: 10uF(M)  VAL2: 50V  (hidden comment: GRM31CR61H106MA12L)
C136  VAL1: 1uF(K)  VAL2: 50V  (hidden comment: GRM188R61H105KAALD)
C137  NOTMOUNT: NOT MOUNT  SIZECODESMD: 1608  (hidden comment: NC_C1608)
C138  VAL2: 50V  VAL1: 1uF(K)  (hidden comment: GRM188R61H105KAALD)
C139  VAL1: 1uF(K)  VAL2: 10V  (hidden comment: GRM188R71A105KA61D)
C140  VAL1: 1uF(K)  VAL2: 50V  (hidden comment: GRM188R61H105KAALD)
C141  VAL1: 1uF(K)  VAL2: 50V  (hidden comment: GRM188R61H105KAALD)
C142  NOTMOUNT: NOT MOUNT  SIZECODESMD: 1608  (hidden comment: NC_C1608)
C143  VAL2: 50V  VAL1: 3300pF(J)  (hidden comment: GRM1885C1H682JA01D)
C144  VAL1: 10uF(K)  VAL2: 25V  (hidden comment: GRM21BC71E106KE11L)
D43  VAL3: CMF02A  USERCOMPTEXT3: TOSHIBA  (hidden comment: CMF05)
D45  USERCOMPTEXT3: TOSHIBA  VAL3: CMS03  (hidden comment: SBD)
D46  CRY82  USERCOMPTEXT3: TOSHIBA
D47  USERCOMPTEXT3: TOSHIBA  VAL3: CUS05F30  (hidden comment: SBD)
D48  KDZVTR2.0B
D49  VAL3: CMF02A  USERCOMPTEXT3: TOSHIBA  (hidden comment: CMF05)
D51  USERCOMPTEXT3: TOSHIBA  VAL3: CMS03  (hidden comment: SBD)
D52  CRY82  USERCOMPTEXT3: TOSHIBA
D53  USERCOMPTEXT3: TOSHIBA  VAL3: CUS05F30  (hidden comment: SBD)
D54  KDZVTR2.0B
D65  NC_TO-247  NOTMOUNT: NOT MOUNT
D66  NC_TO-247  NOTMOUNT: NOT MOUNT
IC15  LP2951D
IC16  TLP5214A  USERCOMPTEXT3: TOSHIBA
IC17  LP2951D  NOTMOUNT: MOUNT
IC18  TLP5214A  USERCOMPTEXT3: TOSHIBA
PS8  G2412S-2WR2
PS9  G2412S-2WR2
Q7  TK49N65W5  USERCOMPTEXT3: TOSHIBA
Q8  TK49N65W5  USERCOMPTEXT3: TOSHIBA
R92  VAL1: 82k(F)  (hidden comment: RK73H1JTTD8202F)
R93  VAL1: 75k(F)  (hidden comment: RK73H1JTTD7502F)
R94  VAL1: 10k(F)  (hidden comment: RK73H1JTTD1002F)
R95  VAL1: 470(J)  (hidden comment: RK73B1JTTD471J)
R96  VAL1: 9.1k(F)  (hidden comment: ERJ3EKF9101V)
R97  NOTMOUNT: NOT MOUNT  SIZECODESMD: 1608  (hidden comment: NC_R1608)
R98  VAL1: 3.3(J)  (hidden comment: ERJ1TYJ100U)
R99  VAL1: 1k(F)  (hidden comment: RK73H1JTTD1001F)
R100  VAL1: 4.7(J)  (hidden comment: ERJ1TYJ470U)
R101  VAL1: 6.8k(F)  (hidden comment: RK73H1JTTD6801F)
R102  VAL1: 6.8k(F)  (hidden comment: RK73H1JTTD6801F)
R103  VAL1: 10k(J)  (hidden comment: RK73B1JTTD103J)
R104  VAL1: 82k(F)  (hidden comment: RK73H1JTTD8202F)
R105  VAL1: 75k(F)  (hidden comment: RK73H1JTTD7502F)
R106  VAL1: 10k(F)  (hidden comment: RK73H1JTTD1002F)
R107  VAL1: 470(J)  (hidden comment: RK73B1JTTD471J)
R108  VAL1: 9.1k(F)  (hidden comment: ERJ3EKF9101V)
R109  NOTMOUNT: NOT MOUNT  SIZECODESMD: 1608  (hidden comment: NC_R1608)
R110  VAL1: 3.3(J)  (hidden comment: ERJ1TYJ100U)
R111  VAL1: 1k(F)  (hidden comment: RK73H1JTTD1001F)
R112  VAL1: 4.7(J)  (hidden comment: ERJ1TYJ470U)
R113  VAL1: 6.8k(F)  (hidden comment: RK73H1JTTD6801F)
R114  VAL1: 6.8k(F)  (hidden comment: RK73H1JTTD6801F)
R115  VAL1: 10k(J)  (hidden comment: RK73B1JTTD103J)
R167  NOTMOUNT: NOT MOUNT  (hidden comment: RK73Z1JTTD)
R168  VAL3: 1608  VAL1: 0  (hidden comment: NC_R1608)
R169  NOTMOUNT: NOT MOUNT  (hidden comment: RK73Z1JTTD)
R170  NOTMOUNT: NOT MOUNT  (hidden comment: RK73Z1JTTD)
R171  SIZECODESMD: 1608  VAL1: 0  (hidden comment: NC_R1608)
R172  NOTMOUNT: NOT MOUNT  (hidden comment: RK73Z1JTTD)
R179  VAL1: 0  (hidden comment: RK73Z2ATTD)
R180  VAL1: 0  (hidden comment: RK73Z2ATTD)
TB6  OP-057
TP32  TP  (value not drawn)
TP33  TP  (value not drawn)
TP34  TP  (value not drawn)
TP35  TP  (value not drawn)
TP36  TP  (value not drawn)
TP37  TP  (value not drawn)
TP38  TP  (value not drawn)
TP39  TP  (value not drawn)
TP40  TP  (value not drawn)
TP41  TP  (value not drawn)
U?#5  DATE: 2026/04/27  DRAWINGNUMBER: RD264-SCHEMATIC-01  TITLE: Full SiC MOSFET 10kW Isolated / Bidirectional DC-DC Converter  FUNCTION: low-voltage side Full Bridge B  SHEETNUMBER: 5/7  REVISION: 01  (hidden comment: WAKU_DEF100)

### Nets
+5V: C119.1 C139.1 IC16.2(VCC1) IC18.2(VCC1) R95.1 R107.1
+12V_Q7: C117.1 C118.1 C120.1 C121.1 IC15.1(OUTPUT) IC16.13(VCC2) R92.1 R101.1 R102.1 R167.2 TP32.1
+12V_Q8: C137.1 C138.1 C140.1 C141.1 IC17.1(OUTPUT) IC18.13(VCC2) R104.1 R113.1 R114.1 R170.2 TP37.1
+24V: C114.1 C134.1 PS8.1(+VIN) PS9.1(+VIN)
GND: C119.2 C139.2 IC16.1(VS1) IC16.4(VS2) IC18.1(VS1) IC18.4(VS2)
GND_24V: C114.2 C134.2 PS8.2(-VIN) PS9.2(-VIN)
GND_Q7: C115.2 C116.2 C118.2 C120.2 C124.2 D48.A IC15.3(SHUTDOWN) IC15.4(GND) IC16.9(VEE1) IC16.12(VEE2) PS8.5(-VOUT) R94.2 R179.2 TP36.1
GND_Q8: C135.2 C136.2 C138.2 C140.2 C144.2 D54.A IC17.3(SHUTDOWN) IC17.4(GND) IC18.9(VEE1) IC18.12(VEE2) PS9.5(-VOUT) R106.2 R180.2 TP41.1
/FLT_OUT_LV: IC16.3(FLT) IC18.3(FLT) ; off-sheet /FLT_OUT_LV
/PWM_6A: IC16.5(K1) IC16.8(K2) R99.2 ; off-sheet /PWM_6A
/PWM_6B: IC18.5(K1) IC18.8(K2) R111.2 ; off-sheet /PWM_6B
LV_DC_N: C130.2 C131.2 C132.2 C133.2 C141.2 C142.2 C143.2 C144.1 D52.A D53.A D54.K(C) D66.A1 D66.A3 IC18.16(VE) Q8.S R113.2 R114.2 R115.2 R180.1 TP40.1 ; off-sheet LV_DC_N
LV_DC_P: C126.1 C127.1 C128.1 C129.1 D43.K(C) D65.K2 Q7.D ; off-sheet LV_DC_P
SIG482: IC16.6(A1) IC16.7(A2) R95.2 R99.1
SIG484: C121.2 C122.2 C123.2 C124.1 D46.A D47.A D48.K(C) D49.K(C) D65.A1 D65.A3 D66.K2 IC16.16(VE) Q7.S Q8.D R101.2 R102.2 R103.2 R179.1 TB6.1 TB6.2 TB6.3 TB6.4 TP35.1
SIG485: C115.1 C116.1 IC15.8(INPUT) R167.1 R168.2 R169.2
SIG489: C117.2 IC15.7(FEEDBACK) R93.2 R94.1
SIG490: C126.2 C127.2 C128.2 C129.2 C130.1 C131.1 C132.1 C133.1
SIG491: PS8.7(+VOUT) R168.1
SIG492: PS8.6(0V) R169.1
SIG493: IC16.11(Vout) R97.2 R98.2 R100.2
SIG494: D43.A R96.1
SIG496: C123.1 D45.A IC16.10(Vclamp) Q7.G R100.1 R103.1 TP34.1
SIG497: C142.1 D52.K(C) D53.K(C) IC18.14(DESAT) R108.2 R109.1 TP38.1
SIG498: PS9.6(0V) R172.1
SIG499: IC18.11(Vout) R109.2 R110.2 R112.2
SIG500: C143.1 D51.A IC18.10(Vclamp) Q8.G R112.1 R115.1 TP39.1
SIG502: D49.A R108.1
SIG504: C122.1 D46.K(C) D47.K(C) IC16.14(DESAT) R96.2 R97.1 TP33.1
SIG508: IC18.6(A1) IC18.7(A2) R107.2 R111.1
SIG509: D45.K(C) R98.1
SIG510: C135.1 C136.1 IC17.8(INPUT) R170.1 R171.2 R172.2
SIG512: PS9.7(+VOUT) R171.1
SIG513: C137.2 IC17.7(FEEDBACK) R105.2 R106.1
SIG514: R104.2 R105.1
SIG515: D51.K(C) R110.1
SIG520: R92.2 R93.1

Not connected (* = marked no-connect by the designer): IC15 2(SENSE) 5(ERROR) 6(VTAP); IC16 15(Vled); IC17 2(SENSE) 5(ERROR) 6(VTAP); IC18 15(Vled)

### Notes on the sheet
- (near R167) 1608
- (near C114) 3216
- 1608
- 2012
- 3216
- (near C116) 1608
- (near R92) 1608
- (near C118) 1608
- (near C120) 1608
- (near R95) 1608
- (near C119) 1608
- (near C121) 1608
- (near R96) 1608
- (near R99) 1608
- (near R98) 6432
- (near R100) 6432
- (near R179) 2012
- L+
- (near R170) 1608
- (near C134) 3216
- (near C136) 1608
- (near R104) 1608
- (near C138) 1608
- (near R107) 1608
- (near C139) 1608
- (near C140) 1608
- (near C141) 1608
- (near R111) 1608
- (near R110) 6432
- (near R112) 6432
- (near R115) 1608
- (near R180) 2012

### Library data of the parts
C114 = C_Dup1: as C82 on sheet 4
C115 C135 = C_Dup1: as C103 on sheet 4
C116 C136 = C_Dup1: as C104 on sheet 4
C117 C137 = C_Dup1: as C105 on sheet 4
C118 = C_Dup1: as C106 on sheet 4
C119 C139 = C_Dup1: as C107 on sheet 4
C120 C140 = C_Dup1: as C108 on sheet 4
C121 C141 = C_Dup1: as C109 on sheet 4
C122 C142 = C_Dup1: as C110 on sheet 4
C123 C143 = C_Dup1: as C91 on sheet 4
C124 = C_Dup1: as C92 on sheet 4
C126 = C_Dup1: ORIGINALSYMBOLORIGIN: (0,4826); COMP: C-CKG57NX7T2W225M500JH; TIME: 14:31:23; UPDATEUSER: t5459927; SAVECOUNT: 1; INSTANCENAME: INS17255321; REFERENCE TEMPLATE: C; COMPONENTNAME: C_C.Normal_package; NOTE: 2.2uF 450V
C127 = C_Dup1: as C95 on sheet 4
C128 = C_Dup1: ORIGINALSYMBOLORIGIN: (0,4826); COMP: C-CKG57NX7T2W225M500JH; TIME: 14:31:23; UPDATEUSER: t5459927; SAVECOUNT: 1; INSTANCENAME: INS17255645; REFERENCE TEMPLATE: C; COMPONENTNAME: C_C.Normal_package; NOTE: 2.2uF 450V
C129 = C_Dup1: ORIGINALSYMBOLORIGIN: (0,4826); COMP: C-CKG57NX7T2W225M500JH; TIME: 14:31:23; UPDATEUSER: t5459927; SAVECOUNT: 1; INSTANCENAME: INS17255762; REFERENCE TEMPLATE: C; COMPONENTNAME: C_C.Normal_package; NOTE: 2.2uF 450V
C130 = C_Dup1: ORIGINALSYMBOLORIGIN: (0,4826); COMP: C-CKG57NX7T2W225M500JH; TIME: 14:31:23; UPDATEUSER: t5459927; SAVECOUNT: 1; INSTANCENAME: INS17255916; REFERENCE TEMPLATE: C; COMPONENTNAME: C_C.Normal_package; NOTE: 2.2uF 450V
C131 = C_Dup1: ORIGINALSYMBOLORIGIN: (0,4826); COMP: C-CKG57NX7T2W225M500JH; TIME: 14:31:23; UPDATEUSER: t5459927; SAVECOUNT: 1; INSTANCENAME: INS17256105; REFERENCE TEMPLATE: C; COMPONENTNAME: C_C.Normal_package; NOTE: 2.2uF 450V
C132 = C_Dup1: as C100 on sheet 4
C133 = C_Dup1: ORIGINALSYMBOLORIGIN: (0,4826); COMP: C-CKG57NX7T2W225M500JH; TIME: 14:31:23; UPDATEUSER: t5459927; SAVECOUNT: 1; INSTANCENAME: INS17256618; REFERENCE TEMPLATE: C; COMPONENTNAME: C_C.Normal_package; NOTE: 2.2uF 450V
C134 = C_Dup1: as C102 on sheet 4
C138 = C_Dup1: as C86 on sheet 4
C144 = C_Dup1: as C112 on sheet 4
D43 D49 = D: as D37 on sheet 4
D45 D47 D51 D53 = SBD: as D33 on sheet 4
D46 = ZD: as D34 on sheet 4
D48 D54 = ZD: UPDATEUSER: t5459927; COMP: D-KDZVTR2.0B; UPDATETIME: 14:31:23; SAVECOUNT: 1; SAVEAREA0: -4630,-153,17114,13055; ORIGINALSYMBOLORIGIN: (0,0); INSTANCENAME: INS17385836; REFERENCE TEMPLATE: D; FUNCN: ZD_ZD.Normal_package
D52 = ZD: UPDATEUSER: t5459927; COMP: D-CRY82; UPDATETIME: 14:31:23; SAVECOUNT: 1; SAVEAREA0: -4630,-153,17114,13055; ORIGINALSYMBOLORIGIN: (0,0); INSTANCENAME: INS17317417; COMPONENTNAME: ZD_ZD.Normal_package
D65 D66 = NC_TO_247: as D63 on sheet 4
IC15 = LP2951D: as IC11 on sheet 4
IC16 IC18 = TLP5214A: as IC12 on sheet 4
IC17 = LP2951D: IC Regurator; COMP: IC-LP2951D_NM; MAKER: Txsas Instruments; TIME: 14:31:24; UPDATEUSER: t5459927; UPDATETIME: 14:27:00; SAVECOUNT: 3; SAVEAREA0: -6711,-14463,34014,2574; OriginalSymbolOrigin: (0,0)
PS8 PS9 = G2412S_2WR2: as PS6 on sheet 4
Q7 = MFNF: as Q6 on sheet 4
Q8 = MFNF: as Q5 on sheet 4
R92 R104 = R: as R80 on sheet 4
R93 R105 = R: as R81 on sheet 4
R94 R106 = R: as R82 on sheet 4
R95 R107 = R: as R83 on sheet 4
R96 R108 = R: as R84 on sheet 4
R97 R109 = R: as R85 on sheet 4
R98 R110 = R: as R86 on sheet 4
R99 R111 = R: as R87 on sheet 4
R100 R112 = R: as R76 on sheet 4
R101 R113 = R: as R89 on sheet 4
R102 R114 = R: as R90 on sheet 4
R103 R115 = R: as R91 on sheet 4
R167 R170 = R: as R164 on sheet 4
R168 R171 = R: as R165 on sheet 4
R169 R172 = R: as R166 on sheet 4
R179 R180 = R: as R178 on sheet 4
TB6 = OP_057: as TB5 on sheet 4
TP32-TP41 = TP: as TP22-TP31 on sheet 4
U?#5 = WAKU_DEF100: PLOTTIME: HH:MM; SAVEAREA0: 204655,-40163,430411,63902; TIME: 14:30:25; UPDATEUSER: t5459927; UPDATETIME: 14:22:34; SAVECOUNT: 7; OriginalSymbolOrigin: (10160,284480); SHTSAVECOUNT: 17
